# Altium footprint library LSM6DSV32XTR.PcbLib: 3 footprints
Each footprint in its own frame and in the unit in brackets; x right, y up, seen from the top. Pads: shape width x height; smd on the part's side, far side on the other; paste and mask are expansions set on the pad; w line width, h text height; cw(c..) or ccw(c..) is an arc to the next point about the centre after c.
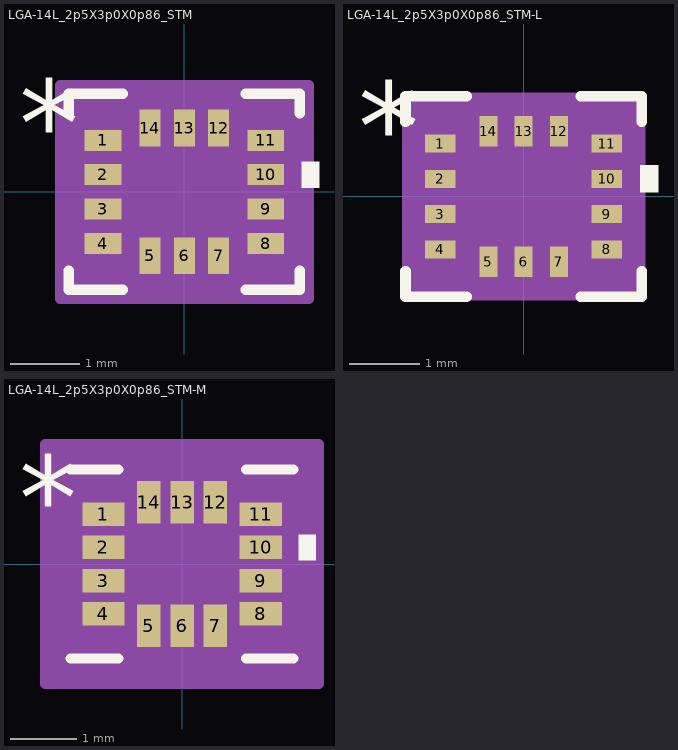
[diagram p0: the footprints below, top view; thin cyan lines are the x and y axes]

## LGA-14L_2p5X3p0X0p86_STM [mil]
pads (14):
  rect 21x12 smd paste+0 mask+0: 1(-46.5,29.53) 2(-46.5,9.84) 3(-46.5,-9.84) 4(-46.5,-29.53) 8(46.5,-29.53) 9(46.5,-9.84) 10(46.5,9.84) 11(46.5,29.53)
  rect 12x21 smd paste+0 mask+0: 5(-19.68,-36.5) 6(0,-36.5) 7(19.68,-36.5) 12(19.68,36.5) 13(0,36.5) 14(-19.68,36.5)
Top Overlay:
  region: 67,17.34 77,17.34 77,2.34 67,2.34
  lines w6: -66,-45.05 -66,-56 -35.2,-56 ; -66,45.05 -66,56 -35.2,56 ; 35.2,-56 66,-56 66,-45.05 ; 35.2,56 66,56 66,45.05
  text "*" at -94.5,14.37 h50
  text ".Designator" at -137.5,-25 h50
Mechanical 13:
  lines w1: -61,1 -11,51 ; -61,-51 61,-51 ; -61,-51 -61,51 ; -61,-51 -61,-51 ; -61,51 61,51 ; -61,51 -61,51 ; 61,-51 61,-51 ; 61,-51 61,51 ; 61,51 61,51 ; -61,-35.53 -61,-23.53 -57,-23.53 -57,-35.53 -61,-35.53 ; -61,-15.84 -61,-3.84 -57,-3.84 -57,-15.84 -61,-15.84 ; -61,3.84 -61,15.84 -57,15.84 -57,3.84 -61,3.84 ; -61,23.53 -61,35.53 -57,35.53 -57,23.53 -61,23.53 ; -25.68,-51 -13.69,-51 -13.69,-47 -25.68,-47 -25.68,-51 ; -25.68,47 -13.69,47 -13.69,51 -25.68,51 -25.68,47 ; -6,-51 6,-51 6,-47 -6,-47 -6,-51 ; -6,47 6,47 6,51 -6,51 -6,47 ; 13.69,-51 25.68,-51 25.68,-47 13.69,-47 13.69,-51 ; 13.69,47 25.68,47 25.68,51 13.69,51 13.69,47 ; 57,-35.53 61,-35.53 61,-23.53 57,-23.53 57,-35.53 ; 57,-15.84 61,-15.84 61,-3.84 57,-3.84 57,-15.84 ; 57,3.84 61,3.84 61,15.84 57,15.84 57,3.84 ; 57,23.53 61,23.53 61,35.53 57,35.53 57,23.53
  text ".Designator" at -137.5,-25 h50
  text "*" at -48.5,14.37 h50
Mechanical 15:
  region: -35.69,-61 -71,-61 -71,-45.53 -71,45.53 -71,61 -35.69,61 35.69,61 71,61 71,45.53 71,-45.53 71,-61 35.69,-61
  lines w6: -71,-45.53 -71,-61 -35.69,-61 ; -71,-45.53 -71,-45.53 ; -71,-45.53 -71,45.53 ; -71,45.53 -71,45.53 ; -71,45.53 -71,61 -35.69,61 ; -35.69,-61 35.69,-61 ; -35.69,-61 -35.69,-61 ; -35.69,61 -35.69,61 ; -35.69,61 35.69,61 ; 35.69,-61 71,-61 71,-45.53 ; 35.69,-61 35.69,-61 ; 35.69,61 35.69,61 ; 35.69,61 71,61 71,45.53 ; 71,-45.53 71,45.53 ; 71,-45.53 71,-45.53 ; 71,45.53 71,45.53
3D body "LGA-14L_2p5X3p0X0p86_STM.step": height 34.09, standoff 0, extent -60.98,-50.98 60.98,50.98

## LGA-14L_2p5X3p0X0p86_STM-L [mil]
pads (14):
  rect 17.06x10.03 smd paste+0 mask+0: 1(-46.5,29.53) 2(-46.5,9.84) 3(-46.5,-9.84) 4(-46.5,-29.53) 8(46.5,-29.53) 9(46.5,-9.84) 10(46.5,9.84) 11(46.5,29.53)
  rect 10.03x17.06 smd paste+0 mask+0: 5(-19.68,-36.5) 6(0,-36.5) 7(19.68,-36.5) 12(19.68,36.5) 13(0,36.5) 14(-19.68,36.5)
Top Overlay:
  region: 65.03,17.34 75.03,17.34 75.03,2.34 65.03,2.34
  lines w6: -66,-41.71 -66,-56 -31.86,-56 ; -66,41.71 -66,56 -31.86,56 ; 31.86,-56 66,-56 66,-41.71 ; 31.86,56 66,56 66,41.71
  text "*" at -92.53,14.37 h50
  text ".Designator" at -137.5,-25 h50
Mechanical 13:
  lines w1: -61,1 -11,51 ; -61,-51 61,-51 ; -61,-51 -61,51 ; -61,-51 -61,-51 ; -61,51 61,51 ; -61,51 -61,51 ; 61,-51 61,-51 ; 61,-51 61,51 ; 61,51 61,51 ; -61,-35.53 -61,-23.53 -57,-23.53 -57,-35.53 -61,-35.53 ; -61,-15.84 -61,-3.84 -57,-3.84 -57,-15.84 -61,-15.84 ; -61,3.84 -61,15.84 -57,15.84 -57,3.84 -61,3.84 ; -61,23.53 -61,35.53 -57,35.53 -57,23.53 -61,23.53 ; -25.68,-51 -13.69,-51 -13.69,-47 -25.68,-47 -25.68,-51 ; -25.68,47 -13.69,47 -13.69,51 -25.68,51 -25.68,47 ; -6,-51 6,-51 6,-47 -6,-47 -6,-51 ; -6,47 6,47 6,51 -6,51 -6,47 ; 13.69,-51 25.68,-51 25.68,-47 13.69,-47 13.69,-51 ; 13.69,47 25.68,47 25.68,51 13.69,51 13.69,47 ; 57,-35.53 61,-35.53 61,-23.53 57,-23.53 57,-35.53 ; 57,-15.84 61,-15.84 61,-3.84 57,-3.84 57,-15.84 ; 57,3.84 61,3.84 61,15.84 57,15.84 57,3.84 ; 57,23.53 61,23.53 61,35.53 57,35.53 57,23.53
  text ".Designator" at -137.5,-25 h50
  text "*" at -50.47,14.37 h50
Mechanical 15:
  region: -28.7,-55 -65,-55 -65,-38.54 -65,38.54 -65,55 -28.7,55 28.7,55 65,55 65,38.54 65,-38.54 65,-55 28.7,-55
  lines w6: -65,-38.54 -65,-55 -28.7,-55 ; -65,-38.54 -65,-38.54 ; -65,-38.54 -65,38.54 ; -65,38.54 -65,38.54 ; -65,38.54 -65,55 -28.7,55 ; -28.7,-55 28.7,-55 ; -28.7,-55 -28.7,-55 ; -28.7,55 -28.7,55 ; -28.7,55 28.7,55 ; 28.7,-55 65,-55 65,-38.54 ; 28.7,-55 28.7,-55 ; 28.7,55 28.7,55 ; 28.7,55 65,55 65,38.54 ; 65,-38.54 65,38.54 ; 65,-38.54 65,-38.54 ; 65,38.54 65,38.54
3D body "LGA-14L_2p5X3p0X0p86_STM.step": height 34.09, standoff 0, extent -60.98,-50.98 60.98,50.98

## LGA-14L_2p5X3p0X0p86_STM-M [mil]
pads (14):
  rect 24.94x13.97 smd paste+0 mask+0: 1(-46.5,29.53) 2(-46.5,9.84) 3(-46.5,-9.84) 4(-46.5,-29.53) 8(46.5,-29.53) 9(46.5,-9.84) 10(46.5,9.84) 11(46.5,29.53)
  rect 13.97x24.94 smd paste+0 mask+0: 5(-19.68,-36.5) 6(0,-36.5) 7(19.68,-36.5) 12(19.68,36.5) 13(0,36.5) 14(-19.68,36.5)
Top Overlay:
  region: 68.97,17.34 78.97,17.34 78.97,2.34 68.97,2.34
  lines w6: -66,-56 -37.72,-56 ; -66,56 -37.72,56 ; 37.72,-56 66,-56 ; 37.72,56 66,56
  text "*" at -96.47,14.37 h50
  text ".Designator" at -137.5,-25 h50
Mechanical 13:
  lines w1: -61,1 -11,51 ; -61,-51 61,-51 ; -61,-51 -61,51 ; -61,-51 -61,-51 ; -61,51 61,51 ; -61,51 -61,51 ; 61,-51 61,-51 ; 61,-51 61,51 ; 61,51 61,51 ; -61,-35.53 -61,-23.53 -57,-23.53 -57,-35.53 -61,-35.53 ; -61,-15.84 -61,-3.84 -57,-3.84 -57,-15.84 -61,-15.84 ; -61,3.84 -61,15.84 -57,15.84 -57,3.84 -61,3.84 ; -61,23.53 -61,35.53 -57,35.53 -57,23.53 -61,23.53 ; -25.68,-51 -13.69,-51 -13.69,-47 -25.68,-47 -25.68,-51 ; -25.68,47 -13.69,47 -13.69,51 -25.68,51 -25.68,47 ; -6,-51 6,-51 6,-47 -6,-47 -6,-51 ; -6,47 6,47 6,51 -6,51 -6,47 ; 13.69,-51 25.68,-51 25.68,-47 13.69,-47 13.69,-51 ; 13.69,47 25.68,47 25.68,51 13.69,51 13.69,47 ; 57,-35.53 61,-35.53 61,-23.53 57,-23.53 57,-35.53 ; 57,-15.84 61,-15.84 61,-3.84 57,-3.84 57,-15.84 ; 57,3.84 61,3.84 61,15.84 57,15.84 57,3.84 ; 57,23.53 61,23.53 61,35.53 57,35.53 57,23.53
  text ".Designator" at -137.5,-25 h50
  text "*" at -46.53,14.37 h50
Mechanical 15:
  region: -46.67,-71 -81,-71 -81,-56.51 -81,56.51 -81,71 -46.67,71 46.67,71 81,71 81,56.51 81,-56.51 81,-71 46.67,-71
  lines w6: -81,-56.51 -81,-71 -46.67,-71 ; -81,-56.51 -81,-56.51 ; -81,-56.51 -81,56.51 ; -81,56.51 -81,56.51 ; -81,56.51 -81,71 -46.67,71 ; -46.67,-71 46.67,-71 ; -46.67,-71 -46.67,-71 ; -46.67,71 -46.67,71 ; -46.67,71 46.67,71 ; 46.67,-71 81,-71 81,-56.51 ; 46.67,-71 46.67,-71 ; 46.67,71 46.67,71 ; 46.67,71 81,71 81,56.51 ; 81,-56.51 81,56.51 ; 81,-56.51 81,-56.51 ; 81,56.51 81,56.51
3D body "LGA-14L_2p5X3p0X0p86_STM.step": height 34.09, standoff 0, extent -60.98,-50.98 60.98,50.98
